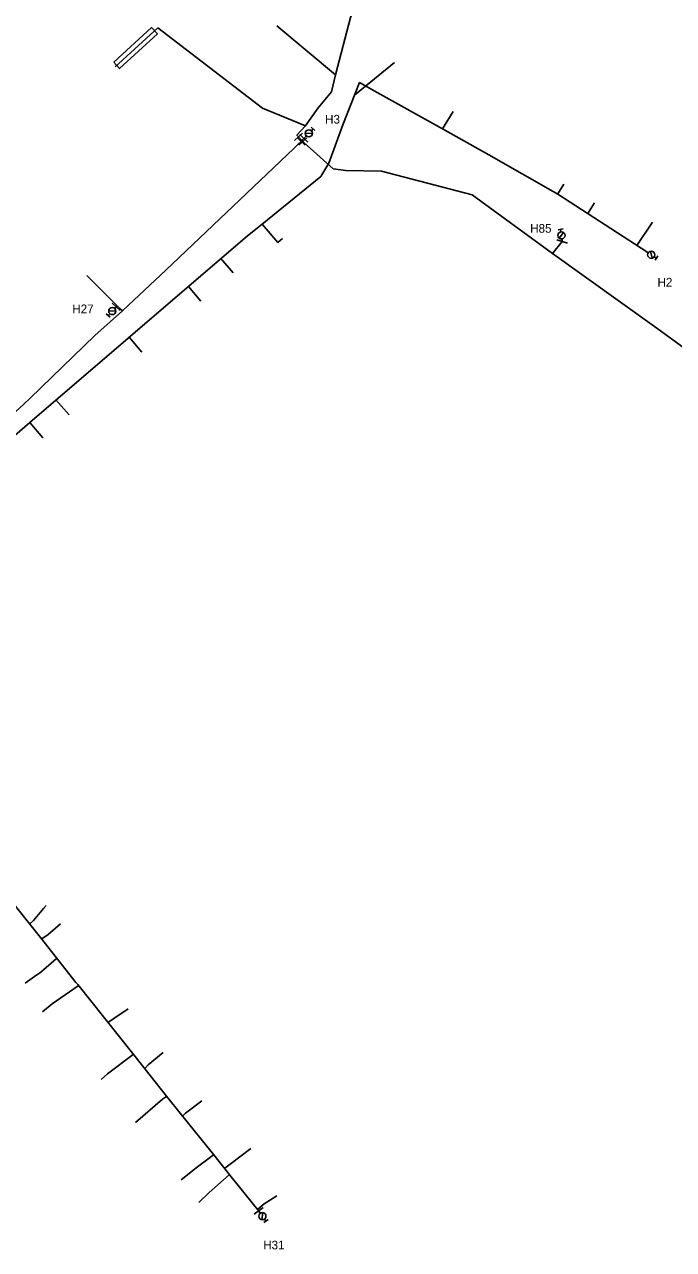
# Model space of a CAD drawing. Extents: x -548873 to -538270, y -1201997 to -1192514.
# Drawn here: x -547113 to -546963.5, y -1195772.5 to -1195490.5 of the extents above; entities that cross this region are included whole.
import ezdxf

# ---------------------------------------------------------------- set-up
doc = ezdxf.new("R2010")
doc.units = 0
for name, color, linetype in [('KN_HRAN_STÁTNÍ', 7, 'Continuous'), ('KN_PARC_Č', 7, 'Continuous'), ('KN_VKP_HRAN_SPORNÁ', 7, 'Continuous'), ('PK_PARC_Čv', 7, 'Continuous'), ('Vrstva 29', 7, 'Continuous'), ('Vrstva 37', 7, 'Continuous')]:
    doc.layers.add(name, color=color, linetype=linetype)

# ---------------------------------------------------------------- blocks, each defined once
blk = doc.blocks.new('160')
at = {"layer": 'KN_HRAN_STÁTNÍ'}
blk.add_circle((0, 0), 0.0458, dxfattribs=at)
blk = doc.blocks.new('147')
at = {"layer": 'KN_HRAN_STÁTNÍ'}
blk.add_line((0, 1.27), (0, -1.27), dxfattribs=at)
blk = doc.blocks.new('133')
at = {"layer": 'KN_HRAN_STÁTNÍ'}
for p, q in [((0.28, 0), (0, 0)), ((0.54, 0.58), (1.7, -0.58)), ((1.94, 0), (2.52, 0)), ((2.52, 0.58), (2.52, -0.58))]:
    blk.add_line(p, q, dxfattribs=at)
blk.add_circle((1.11, 0), 0.825, dxfattribs=at)
blk = doc.blocks.new('150')
at = {"layer": 'KN_HRAN_STÁTNÍ'}
blk.add_line((0, 1.27), (0, -1.27), dxfattribs=at)

msp = doc.modelspace()

# ---------------------------------------------------------------- linework, layer by layer
at = {"layer": 'KN_PARC_Č'}
for points in [[(-547082.284, -1195491.301), (-547092.106, -1195500.262)], [(-547048.312, -1195513.91), (-547048.469, -1195513.784), (-547048.637, -1195513.66), (-547058.174, -1195509.797), (-547082.284, -1195491.301)], [(-547041.37, -1195502.14), (-547054.867, -1195490.836)], [(-547036.959, -1195506.8), (-547027.72, -1195499.259)], [(-547016.716, -1195514.537), (-547014.209, -1195510.509)], [(-546990.176, -1195529.53), (-546988.735, -1195527.238)], [(-546983.236, -1195534.035), (-546981.714, -1195531.536)], [(-547058.208, -1195536.47), (-547054.597, -1195540.722), (-547053.52, -1195539.753)], [(-546971.919, -1195541.388), (-546968.382, -1195536.008)], [(-547067.731, -1195544.412), (-547064.925, -1195547.713)], [(-547090.42, -1195556.45), (-547090.99, -1195555.87), (-547091.613, -1195555.238), (-547098.566, -1195548.272)], [(-547075.227, -1195550.833), (-547072.323, -1195554.172)], [(-547088.856, -1195562.509), (-547085.896, -1195565.957)], [(-547105.707, -1195576.945), (-547102.674, -1195580.394)], [(-547111.758, -1195582.13), (-547108.73, -1195585.636)], [(-547111.774, -1195697.529), (-547111.607, -1195697.403), (-547110.88, -1195696.723), (-547108.578, -1195694), (-547107.981, -1195693.289)], [(-547109.017, -1195700.998), (-547108.966, -1195700.957), (-547107.519, -1195699.986), (-547104.692, -1195697.552)], [(-547105.503, -1195705.451), (-547105.579, -1195705.51), (-547109.175, -1195708.651), (-547110.623, -1195709.621), (-547112.83, -1195711.161)], [(-547100.492, -1195711.731), (-547100.575, -1195711.793), (-547106.575, -1195715.964), (-547108.821, -1195717.816)], [(-547093.701, -1195720.279), (-547093.576, -1195720.161), (-547092.398, -1195719.299), (-547089.102, -1195717.101)], [(-547087.879, -1195727.56), (-547087.941, -1195727.615), (-547093.818, -1195732.039), (-547095.299, -1195733.38)], [(-547085.28, -1195730.827), (-547085.127, -1195730.707), (-547084.503, -1195730.009), (-547080.995, -1195727.162)], [(-547080.172, -1195737.251), (-547080.226, -1195737.298), (-547081.183, -1195737.867), (-547087.408, -1195743.237)], [(-547076.568, -1195741.755), (-547076.518, -1195741.709), (-547075.906, -1195741.117), (-547072.135, -1195738.304)], [(-547069.388, -1195750.676), (-547069.435, -1195750.712), (-547070.465, -1195751.487), (-547073.12, -1195753.478), (-547076.881, -1195756.476)], [(-547066.876, -1195753.855), (-547066.806, -1195753.796), (-547065.602, -1195752.843), (-547060.8, -1195749.204)], [(-547065.763, -1195755.264), (-547065.829, -1195755.321), (-547070.428, -1195759.373), (-547072.814, -1195761.669)], [(-547059.318, -1195763.23), (-547059.246, -1195763.17), (-547057.789, -1195762.003), (-547054.836, -1195760.147)]]:
    msp.add_lwpolyline(points, dxfattribs=at)
at = {"layer": 'KN_VKP_HRAN_SPORNÁ'}
for points in [[(-546947.943, -1195374.483), (-546965.435, -1195393.845), (-546969.264, -1195398.243), (-547002.142, -1195436.005), (-547019.582, -1195459.325), (-547032.076, -1195476.946), (-547033.1, -1195478.39), (-547037.92, -1195488.9), (-547041.37, -1195502.14), (-547042.28, -1195506.03), (-547045.31, -1195509.717)], [(-547160.61, -1195627.54), (-547141.63, -1195608.78), (-547127.359, -1195595.616), (-547111.746, -1195582.119), (-547089.115, -1195562.731), (-547061.579, -1195539.141), (-547058.208, -1195536.47), (-547044.74, -1195525.49), (-547042.872, -1195522.421), (-547039.65, -1195513.61), (-547035.807, -1195503.886), (-547031.746, -1195506.151), (-547016.716, -1195514.537), (-547006.025, -1195520.502), (-546990.119, -1195529.563), (-546969.644, -1195542.866)], [(-547045.31, -1195509.717), (-547048.312, -1195513.91), (-547050.218, -1195515.966), (-547049.843, -1195516.364)], [(-547167.71, -1195624.93), (-547167.11, -1195624.49), (-547166.098, -1195623.905), (-547164.377, -1195622.558), (-547163.1, -1195621.56), (-547147.98, -1195608.532), (-547137.07, -1195599.13), (-547132.96, -1195595.64), (-547118.599, -1195582.875), (-547113.099, -1195577.925), (-547111.617, -1195576.495), (-547096.74, -1195562.14), (-547090.42, -1195556.45), (-547087.773, -1195554), (-547080.425, -1195547.036), (-547050.942, -1195519.091), (-547050.01, -1195518.153), (-547049.27, -1195517.41)], [(-547049.843, -1195516.364), (-547049.069, -1195517.207)], [(-547049.27, -1195517.41), (-547049.069, -1195517.207)], [(-547049.069, -1195517.207), (-547048.86, -1195517.44)], [(-547048.86, -1195517.44), (-547048.649, -1195517.669), (-547041.84, -1195523.73), (-547038.94, -1195524.14), (-547030.78, -1195524.27), (-547009.84, -1195529.76), (-546991.38, -1195543.2), (-546967.92, -1195560), (-546954.12, -1195570.03), (-546930.91, -1195586.12), (-546908.32, -1195602.75), (-546885.43, -1195619.15), (-546852.86, -1195642.38), (-546840.498, -1195646.62), (-546839.528, -1195647.03), (-546810.006, -1195661.482), (-546638.949, -1195753.557)], [(-547144.665, -1195654.487), (-547144.454, -1195654.703), (-547144.513, -1195655.474), (-547143.317, -1195657.085), (-547139.408, -1195662.241), (-547134.331, -1195668.939), (-547126.864, -1195678.49), (-547126.412, -1195679.057), (-547119.021, -1195688.403), (-547118.07, -1195689.608), (-547108.983, -1195701.041), (-547101.095, -1195711.038), (-547100.661, -1195711.518), (-547094.705, -1195719.024), (-547087.803, -1195727.655), (-547080.248, -1195737.156), (-547076.81, -1195741.454), (-547069.388, -1195750.676), (-547065.365, -1195755.767), (-547059.201, -1195763.374)]]:
    msp.add_lwpolyline(points, dxfattribs=at)
at = {"layer": 'PK_PARC_Čv'}
for points in [[(-547049.069, -1195517.207), (-547048.25, -1195516.36)], [(-546991.38, -1195543.2), (-546989.12, -1195540.47), (-546989.16, -1195540.16)], [(-546969.644, -1195542.866), (-546969.57, -1195542.914)], [(-547091.613, -1195555.238), (-547091.84, -1195555.48), (-547091.998, -1195555.655)], [(-547059.201, -1195763.374), (-547058.823, -1195763.909)]]:
    msp.add_lwpolyline(points, dxfattribs=at)
at = {"layer": 'Vrstva 37'}
msp.add_lwpolyline([(-547092.409, -1195499.185), (-547083.684, -1195491.225), (-547082.336, -1195492.702), (-547091.061, -1195500.662), (-547092.409, -1195499.185)], dxfattribs=at)

# ---------------------------------------------------------------- block references
at = {"layer": 'PK_PARC_Čv'}
for name, p, xscale, yscale, rotation in [('133', (-547048.25, -1195516.36), 1.0000000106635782, 1.0000000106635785, 45.99999834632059), ('150', (-547048.632, -1195516.755), 1.0000000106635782, 1.0000000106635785, 45.99999834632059), ('150', (-546989.12, -1195540.47), 0.9999999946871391, 0.9999999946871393, 73.99999975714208), ('133', (-546989.16, -1195540.16), 0.9999999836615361, 0.9999999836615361, 98.00000038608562), ('133', (-546969.57, -1195542.914), 0.9999999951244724, 0.9999999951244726, -33.000001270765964), ('133', (-547091.998, -1195555.655), 1.0000000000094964, 1.0000000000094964, -132.0000013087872), ('150', (-547091.84, -1195555.48), 1.0000000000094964, 1.0000000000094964, 47.99999869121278), ('150', (-547059.055, -1195763.581), 1.000000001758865, 1.000000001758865, -54.00000066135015), ('133', (-547058.823, -1195763.909), 1.000000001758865, 1.000000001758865, -54.00000066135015)]:
    msp.add_blockref(name, p, dxfattribs=dict(at, xscale=xscale, yscale=yscale, rotation=rotation))
at = {"layer": 'Vrstva 29'}
for name, p, xscale, yscale, rotation in [('147', (-547049.843, -1195516.364), 1.00000000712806, 1.00000000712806, -46.99999943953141), ('147', (-547049.27, -1195517.41), 1.0000000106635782, 1.0000000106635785, 45.99999834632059), ('147', (-547048.86, -1195517.44), 1.00000000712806, 1.00000000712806, -46.99999943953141), ('160', (-547049.069, -1195517.207), 1.000000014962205, 1.0000000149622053, -0.9999999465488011), ('160', (-546969.644, -1195542.866), 0.9999999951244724, 0.9999999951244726, -33.000001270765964), ('160', (-547059.201, -1195763.374), 1.0000000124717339, 1.0000000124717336, -49.99999868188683)]:
    msp.add_blockref(name, p, dxfattribs=dict(at, xscale=xscale, yscale=yscale, rotation=rotation))

# ---------------------------------------------------------------- texts
at = {"layer": 'PK_PARC_Čv'}
for s, p in [('H3', (-547043.73, -1195513.33)), ('H85', (-546996.51, -1195538.45)), ('H2', (-546967.196, -1195550.844)), ('H27', (-547101.938, -1195556.975)), ('H31', (-547057.983, -1195772.459))]:
    msp.add_text(s, height=2, dxfattribs=at).set_placement(p)

doc.saveas('drawing.dxf')
